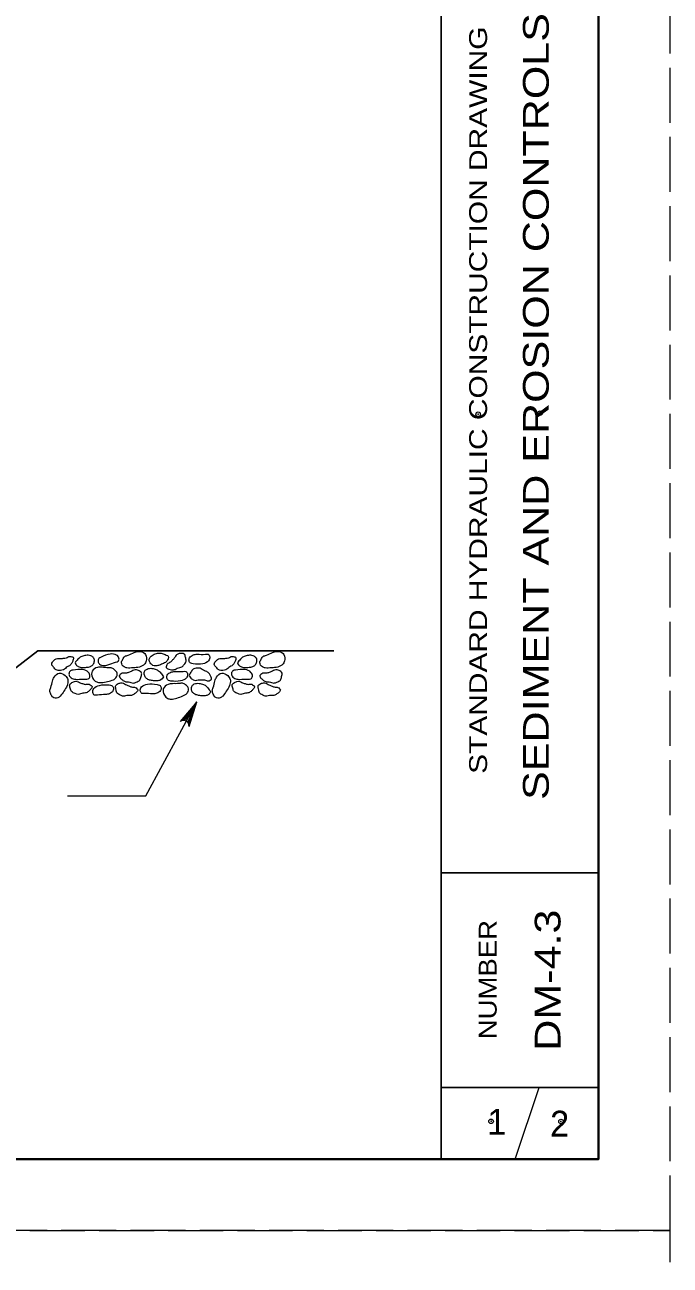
# Model space of a CAD drawing. Extents: x 1043.1 to 1101.1, y 672.4 to 716.4.
# Drawn here: x 1072.63 to 1077.14, y 694.15 to 702.82 of the extents above; entities that cross this region are included whole.
import ezdxf
from ezdxf.enums import TextEntityAlignment as Align

# ---------------------------------------------------------------- set-up
doc = ezdxf.new("R2010")
doc.units = 0
doc.header["$LTSCALE"] = 0.064
doc.header["$PDMODE"] = 32
doc.header["$PDSIZE"] = 0.032
doc.linetypes.add('LONG_DASHED', pattern=[7.5, 6, -1.5])
doc.layers.add('1', color=7, linetype='Continuous', lineweight=13)

msp = doc.modelspace()

# ---------------------------------------------------------------- linework, layer by layer
at = {"layer": '1', "lineweight": 25}
for p, q in [((1075.54425, 694.89508), (1075.54425, 715.89508)), ((1076.64425, 715.89508), (1076.64425, 694.89508)), ((1072.72475, 698.44833), (1071.86283, 697.78133)), ((1072.72475, 698.44833), (1074.79383, 698.44833)), ((1076.64425, 696.89508), (1075.54425, 696.89508)), ((1076.64425, 695.39508), (1075.54425, 695.39508))]:
    msp.add_line(p, q, dxfattribs=at)
at = {"layer": '1'}
for p, q in [((1073.738, 697.96117), (1073.83508, 698.09183)), ((1073.75017, 697.96058), (1073.83508, 698.09183)), ((1073.76125, 697.95667), (1073.83508, 698.09183)), ((1073.76367, 697.96158), (1073.83442, 698.08975)), ((1073.77258, 697.94742), (1073.83508, 698.09183)), ((1073.77867, 697.93683), (1073.83508, 698.09183)), ((1076.06092, 694.89508), (1076.22758, 695.39508))]:
    msp.add_line(p, q, dxfattribs=at)
at = {"layer": '1', "linetype": 'LONG_DASHED'}
for points in [[(1043.14425, 694.39508), (1077.14425, 694.39508), (1077.14425, 716.39508), (1043.14425, 716.39508)], [(1043.14425, 672.39508), (1077.14425, 672.39508), (1077.14425, 694.39508), (1043.14425, 694.39508)]]:
    msp.add_lwpolyline(points, close=True, dxfattribs=at)
at = {"layer": '1', "lineweight": 25}
msp.add_lwpolyline([(1076.64425, 694.89508), (1045.14425, 694.89508), (1045.14425, 715.89508)], dxfattribs=at)
at = {"layer": '1', "lineweight": 40}
msp.add_lwpolyline([(1045.14425, 715.89508), (1076.64425, 715.89508), (1076.64425, 694.89508), (1045.14425, 694.89508)], close=True, dxfattribs=at)
msp.add_lwpolyline([(1076.64425, 694.89508), (1045.14425, 694.89508), (1045.14425, 715.89508)], dxfattribs=at)
at = {"layer": '1'}
for points in [[(1072.93225, 697.43392), (1073.47842, 697.43392), (1073.83508, 698.09183)], [(1073.781, 697.91842), (1073.83508, 698.09183), (1073.7185, 697.95267)]]:
    msp.add_lwpolyline(points, dxfattribs=at)
msp.add_arc((1073.74279, 697.92301), 0.03845, 353.38859, 129.21471, dxfattribs=at)
for points in [[(1072.9615, 698.36108), (1072.96992, 698.38067), (1072.97075, 698.402), (1072.961, 698.40625), (1072.947, 698.40883), (1072.92342, 698.39867), (1072.90208, 698.39508), (1072.87842, 698.39317), (1072.86175, 698.39442), (1072.84392, 698.38708), (1072.82617, 698.36733), (1072.82133, 698.35333), (1072.83475, 698.333), (1072.85325, 698.31375), (1072.882, 698.31075), (1072.90308, 698.314), (1072.93025, 698.335), (1072.94608, 698.34333), (1072.9615, 698.36108)], [(1073.10875, 698.34875), (1073.09117, 698.3375), (1073.06517, 698.33225), (1073.03425, 698.33125), (1073.00675, 698.33692), (1072.99208, 698.34842), (1072.98442, 698.36408), (1072.99408, 698.37742), (1073.01517, 698.399), (1073.03775, 698.41075), (1073.06842, 698.41633), (1073.10175, 698.40908), (1073.11617, 698.39508), (1073.11858, 698.3715), (1073.10875, 698.34875)], [(1073.21458, 698.34883), (1073.18533, 698.34442), (1073.1555, 698.3545), (1073.14542, 698.37292), (1073.15083, 698.39292), (1073.16583, 698.40258), (1073.22933, 698.42475), (1073.27425, 698.418), (1073.29133, 698.39492), (1073.28567, 698.37425), (1073.26792, 698.3675), (1073.21458, 698.34883)], [(1073.45325, 698.34133), (1073.47158, 698.35592), (1073.483, 698.38708), (1073.47125, 698.42967), (1073.42758, 698.4425), (1073.39825, 698.43533), (1073.35492, 698.41658), (1073.33292, 698.40883), (1073.31833, 698.38908), (1073.30925, 698.36433), (1073.32767, 698.3345), (1073.34708, 698.328), (1073.38992, 698.32883), (1073.43425, 698.33425), (1073.45325, 698.34133)], [(1073.52808, 698.3455), (1073.54883, 698.34233), (1073.57467, 698.348), (1073.60342, 698.35958), (1073.62617, 698.37583), (1073.63492, 698.39242), (1073.63575, 698.40975), (1073.62142, 698.418), (1073.59342, 698.42917), (1073.568, 698.43092), (1073.53775, 698.42342), (1073.51017, 698.4035), (1073.50258, 698.38467), (1073.51, 698.36242), (1073.52808, 698.3455)], [(1073.65958, 698.31517), (1073.63883, 698.31992), (1073.62075, 698.33158), (1073.62317, 698.34208), (1073.62908, 698.35508), (1073.65108, 698.36833), (1073.6665, 698.3835), (1073.68158, 698.40175), (1073.6905, 698.416), (1073.70667, 698.42608), (1073.73317, 698.42917), (1073.74733, 698.42483), (1073.75617, 698.40217), (1073.761, 698.37608), (1073.74658, 698.35067), (1073.73183, 698.33558), (1073.699, 698.32567), (1073.683, 698.31758), (1073.65958, 698.31517)], [(1073.83833, 698.42392), (1073.80942, 698.41842), (1073.7845, 698.39892), (1073.78108, 698.37817), (1073.79308, 698.36125), (1073.81025, 698.35692), (1073.87733, 698.357), (1073.9175, 698.37817), (1073.92617, 698.40558), (1073.91408, 698.42325), (1073.895, 698.42392), (1073.83833, 698.42392)], [(1074.097, 698.36108), (1074.10542, 698.38067), (1074.10625, 698.402), (1074.0965, 698.40625), (1074.0825, 698.40883), (1074.05892, 698.39867), (1074.03758, 698.39508), (1074.01392, 698.39317), (1073.99725, 698.39442), (1073.97942, 698.38708), (1073.96167, 698.36733), (1073.95683, 698.35333), (1073.97025, 698.333), (1073.98875, 698.31375), (1074.0175, 698.31075), (1074.03858, 698.314), (1074.06575, 698.335), (1074.08158, 698.34333), (1074.097, 698.36108)], [(1074.24425, 698.34875), (1074.22667, 698.3375), (1074.20067, 698.33225), (1074.16975, 698.33125), (1074.14225, 698.33692), (1074.12758, 698.34842), (1074.11992, 698.36408), (1074.12958, 698.37742), (1074.15067, 698.399), (1074.17325, 698.41075), (1074.20392, 698.41633), (1074.23725, 698.40908), (1074.25167, 698.39508), (1074.25408, 698.3715), (1074.24425, 698.34875)], [(1074.42008, 698.34133), (1074.43842, 698.35592), (1074.44983, 698.38708), (1074.43808, 698.42967), (1074.39442, 698.4425), (1074.36508, 698.43533), (1074.32175, 698.41658), (1074.29975, 698.40883), (1074.28517, 698.38908), (1074.27608, 698.36433), (1074.2945, 698.3345), (1074.31392, 698.328), (1074.35675, 698.32883), (1074.40108, 698.33425), (1074.42008, 698.34133)], [(1072.93417, 698.2235), (1072.93358, 698.24692), (1072.91558, 698.27492), (1072.87442, 698.29108), (1072.83808, 698.26408), (1072.82625, 698.23633), (1072.81483, 698.19033), (1072.80792, 698.16792), (1072.81492, 698.14442), (1072.82917, 698.12242), (1072.864, 698.11917), (1072.88083, 698.13075), (1072.90617, 698.1655), (1072.9285, 698.20417), (1072.93417, 698.2235)], [(1073.0015, 698.24733), (1072.97225, 698.25142), (1072.94642, 698.26967), (1072.94208, 698.29025), (1072.95308, 698.30783), (1072.97008, 698.31275), (1073.03725, 698.31592), (1073.07825, 698.2965), (1073.08825, 698.26967), (1073.07683, 698.2515), (1073.05792, 698.25), (1073.0015, 698.24733)], [(1073.14742, 698.22683), (1073.12567, 698.23533), (1073.10542, 698.26167), (1073.10392, 698.30592), (1073.14167, 698.331), (1073.172, 698.33292), (1073.219, 698.328), (1073.24242, 698.32692), (1073.26217, 698.3125), (1073.278, 698.29175), (1073.26933, 698.25767), (1073.25275, 698.24567), (1073.21175, 698.23367), (1073.16775, 698.22567), (1073.14742, 698.22683)], [(1073.31892, 698.24058), (1073.30308, 698.255), (1073.29342, 698.274), (1073.3005, 698.28183), (1073.31217, 698.29025), (1073.33783, 698.29083), (1073.35875, 698.29633), (1073.38092, 698.30467), (1073.39567, 698.31275), (1073.41483, 698.31358), (1073.43933, 698.303), (1073.44942, 698.29225), (1073.44575, 698.26825), (1073.437, 698.24292), (1073.41225, 698.22808), (1073.39175, 698.22233), (1073.35833, 698.23), (1073.34042, 698.231), (1073.31892, 698.24058)], [(1073.47625, 698.26083), (1073.493, 698.24808), (1073.51833, 698.24075), (1073.54917, 698.23733), (1073.57708, 698.24083), (1073.59258, 698.25117), (1073.60158, 698.26625), (1073.59292, 698.28017), (1073.57358, 698.30333), (1073.55192, 698.31708), (1073.52175, 698.32483), (1073.48808, 698.32033), (1073.4725, 698.3075), (1073.46825, 698.28425), (1073.47625, 698.26083)], [(1073.68308, 698.30325), (1073.654, 698.29775), (1073.62917, 698.27833), (1073.62567, 698.25758), (1073.63767, 698.24058), (1073.65483, 698.23642), (1073.72192, 698.2365), (1073.76217, 698.25758), (1073.77092, 698.285), (1073.75867, 698.30267), (1073.73975, 698.30325), (1073.68308, 698.30325)], [(1073.92308, 698.28617), (1073.93383, 698.26775), (1073.93742, 698.24675), (1073.92817, 698.24117), (1073.91458, 698.23683), (1073.88992, 698.24383), (1073.86842, 698.24492), (1073.84467, 698.24358), (1073.82825, 698.24033), (1073.80983, 698.24517), (1073.78975, 698.26267), (1073.78308, 698.27592), (1073.79383, 698.29767), (1073.80967, 698.31917), (1073.83783, 698.32592), (1073.859, 698.32533), (1073.88867, 698.308), (1073.90542, 698.30175), (1073.92308, 698.28617)], [(1074.06967, 698.2235), (1074.06908, 698.24692), (1074.05108, 698.27492), (1074.00992, 698.29108), (1073.97358, 698.26408), (1073.96175, 698.23633), (1073.95033, 698.19033), (1073.94342, 698.16792), (1073.95042, 698.14442), (1073.96467, 698.12242), (1073.9995, 698.11917), (1074.01633, 698.13075), (1074.04167, 698.1655), (1074.064, 698.20417), (1074.06967, 698.2235)], [(1074.137, 698.24733), (1074.10775, 698.25142), (1074.08192, 698.26967), (1074.07758, 698.29025), (1074.08858, 698.30783), (1074.10558, 698.31275), (1074.17275, 698.31592), (1074.21375, 698.2965), (1074.22375, 698.26967), (1074.21233, 698.2515), (1074.19342, 698.25), (1074.137, 698.24733)], [(1074.3015, 698.24058), (1074.28567, 698.255), (1074.276, 698.274), (1074.28308, 698.28183), (1074.29475, 698.29025), (1074.32042, 698.29083), (1074.34133, 698.29633), (1074.3635, 698.30467), (1074.37825, 698.31275), (1074.39742, 698.31358), (1074.42192, 698.303), (1074.432, 698.29225), (1074.42833, 698.26825), (1074.41958, 698.24292), (1074.39483, 698.22808), (1074.37433, 698.22233), (1074.34092, 698.23), (1074.323, 698.231), (1074.3015, 698.24058)], [(1073.07875, 698.16342), (1073.094, 698.17833), (1073.10317, 698.19758), (1073.09583, 698.20525), (1073.084, 698.21325), (1073.05842, 698.21308), (1073.03725, 698.218), (1073.01483, 698.22558), (1072.99992, 698.233), (1072.98067, 698.23333), (1072.95667, 698.22208), (1072.94675, 698.211), (1072.95108, 698.18708), (1072.96058, 698.16217), (1072.98592, 698.14817), (1073.00658, 698.143), (1073.03975, 698.15158), (1073.0575, 698.15308), (1073.07875, 698.16342)], [(1073.19658, 698.141), (1073.2255, 698.14775), (1073.24942, 698.16833), (1073.25192, 698.18925), (1073.23942, 698.20575), (1073.22192, 698.20908), (1073.15458, 698.20592), (1073.11558, 698.183), (1073.10817, 698.15525), (1073.12108, 698.13825), (1073.14008, 698.13842), (1073.19658, 698.141)], [(1073.39458, 698.14308), (1073.4115, 698.15617), (1073.42275, 698.17417), (1073.41633, 698.18267), (1073.40542, 698.19192), (1073.37983, 698.19458), (1073.3595, 698.20175), (1073.33792, 698.21175), (1073.32392, 698.22092), (1073.30483, 698.22333), (1073.27967, 698.21475), (1073.2685, 698.20483), (1073.27033, 698.18058), (1073.27717, 698.15483), (1073.30067, 698.13792), (1073.32058, 698.13058), (1073.35458, 698.13558), (1073.37242, 698.13517), (1073.39458, 698.14308)], [(1073.52642, 698.14658), (1073.55558, 698.15083), (1073.58133, 698.16925), (1073.5855, 698.18992), (1073.57442, 698.20733), (1073.55742, 698.21217), (1073.49008, 698.21475), (1073.44925, 698.19525), (1073.43942, 698.16825), (1073.45092, 698.15017), (1073.46992, 698.14883), (1073.52642, 698.14658)], [(1073.65467, 698.10925), (1073.632, 698.11475), (1073.60842, 698.13825), (1073.60125, 698.18175), (1073.63533, 698.21175), (1073.66492, 698.21767), (1073.71217, 698.219), (1073.73558, 698.22117), (1073.757, 698.2095), (1073.77558, 698.19092), (1073.77142, 698.15592), (1073.75658, 698.14192), (1073.71742, 698.12458), (1073.675, 698.11075), (1073.65467, 698.10925)], [(1073.80592, 698.15617), (1073.82267, 698.1435), (1073.848, 698.13608), (1073.87883, 698.13267), (1073.90658, 698.13608), (1073.92217, 698.14642), (1073.93108, 698.16142), (1073.92242, 698.17542), (1073.90308, 698.19867), (1073.8815, 698.21233), (1073.85142, 698.22008), (1073.81775, 698.21558), (1073.80217, 698.20275), (1073.79792, 698.17958), (1073.80592, 698.15617)], [(1074.21425, 698.16342), (1074.2295, 698.17833), (1074.23867, 698.19758), (1074.23133, 698.20525), (1074.2195, 698.21325), (1074.19392, 698.21308), (1074.17275, 698.218), (1074.15033, 698.22558), (1074.13542, 698.233), (1074.11617, 698.23333), (1074.09217, 698.22208), (1074.08225, 698.211), (1074.08658, 698.18708), (1074.09608, 698.16217), (1074.12142, 698.14817), (1074.14208, 698.143), (1074.17525, 698.15158), (1074.193, 698.15308), (1074.21425, 698.16342)], [(1074.39117, 698.14308), (1074.40808, 698.15617), (1074.41933, 698.17417), (1074.41292, 698.18267), (1074.402, 698.19192), (1074.37642, 698.19458), (1074.35608, 698.20175), (1074.3345, 698.21175), (1074.3205, 698.22092), (1074.30142, 698.22333), (1074.27625, 698.21475), (1074.26508, 698.20483), (1074.26692, 698.18058), (1074.27375, 698.15483), (1074.29725, 698.13792), (1074.31717, 698.13058), (1074.35117, 698.13558), (1074.369, 698.13517), (1074.39117, 698.14308)]]:
    msp.add_spline(points, degree=3, dxfattribs=at)
for p in [(1075.80167, 700.10108), (1076.2345, 700.10842), (1075.89233, 695.15883), (1076.38075, 695.15783)]:
    msp.add_point(p, dxfattribs=at)

# ---------------------------------------------------------------- texts
for s, height, width, p in [('SEDIMENT AND EROSION CONTROLS', 0.18, 1.25, (1076.29542, 700.15525)), ('STANDARD HYDRAULIC CONSTRUCTION DRAWING', 0.125, 1.25, (1075.86417, 700.19912)), ('NUMBER', 0.125, 1.15, (1075.93125, 696.14917)), ('DM-4.3', 0.18, 1.25, (1076.37758, 696.14542))]:
    msp.add_text(s, height=height, rotation=90, dxfattribs=dict(at, width=width)).set_placement(p, align=Align.CENTER)
for s, p in [('1', (1075.9321, 695.06517)), ('2', (1076.37154, 695.05258))]:
    msp.add_text(s, height=0.18, dxfattribs=at).set_placement(p, align=Align.CENTER)

doc.saveas('drawing.dxf')
